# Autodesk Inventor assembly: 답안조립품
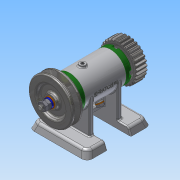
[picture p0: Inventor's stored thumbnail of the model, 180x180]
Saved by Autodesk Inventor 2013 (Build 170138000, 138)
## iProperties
Created: 2016-07
Part Number: 답안조립품
Document SubType Name: Assembly
Designer: Administrator
Author: Administrator
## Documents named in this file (15)
- C:\Users\Administrator\Desktop\460708V1002\답안조립품.iam
- C:\Users\Administrator\Desktop\460708V1002\본체.ipt
- C:\Users\Administrator\Desktop\460708V1002\베어링 15 x 32 x 9.ipt
- C:\Users\Administrator\Desktop\460708V1002\축.ipt
- C:\Users\Administrator\Desktop\460708V1002\키 3 x 3 x 12.ipt
- C:\Users\Administrator\Desktop\460708V1002\V벨트풀리.ipt
- C:\Users\Administrator\Desktop\460708V1002\스퍼기어.ipt
- C:\Users\Administrator\Desktop\460708V1002\와셔 8x17.ipt
- C:\Users\Administrator\Desktop\460708V1002\스프링와셔 8.ipt
- C:\Users\Administrator\Desktop\460708V1002\너트 M 8.ipt
- C:\Users\Administrator\Desktop\460708V1002\커버.ipt
- C:\Users\Administrator\Desktop\460708V1002\오일 실 15 25 7.ipt
- C:\Users\Administrator\Desktop\460708V1002\볼트 M4 x 12.ipt
- C:\Users\Administrator\Desktop\460708V1002\볼트 M 6 x 8.ipt
- C:\Users\Administrator\Desktop\460708V1002\와셔 6x11.5.ipt
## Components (11 placed, 3 different names)
1. KS B 2023 6002 - 15 x 32 x 9:1
2. KS B 2023 6002 - 15 x 32 x 9:2
3. V벨트풀리:1
4. ISO 4762 M4 x 12:2
5. ISO 4762 M4 x 12:1
6. ISO 4762 M4 x 12:3
7. ISO 4762 M4 x 12:4
8. ISO 4762 M4 x 12:5
9. ISO 4762 M4 x 12:6
10. ISO 4762 M4 x 12:7
11. ISO 4762 M4 x 12:8
